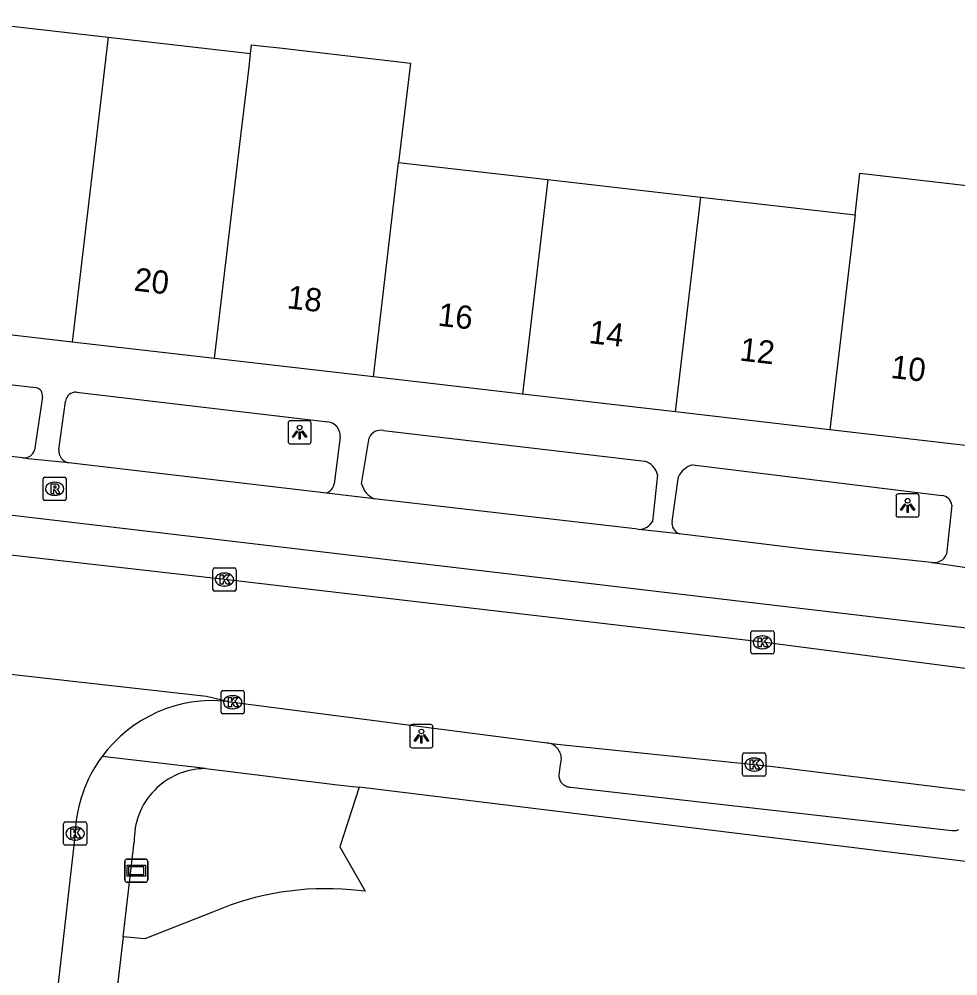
# Model space of a CAD drawing. Extents: x 161696 to 162377, y 380761 to 381673.
# Drawn here: x 162185.51 to 162225.99, y 380898.88 to 380940.12 of the extents above; entities that cross this region are included whole.
import ezdxf

# ---------------------------------------------------------------- set-up
doc = ezdxf.new("R2010")
doc.units = 0
for name, color, linetype in [('IMGEO_Groenvoorziening', 7, 'Continuous'), ('IMGEO_Kolk', 7, 'Continuous'), ('IMGEO_Lichtpunt', 7, 'Continuous'), ('IMGEO_Pand', 7, 'Continuous'), ('IMGEO_Pand_nummerreeks', 7, 'Continuous'), ('IMGEO_Rijbaan_lokaal_open', 7, 'Continuous'), ('IMGEO_Rioolput', 7, 'Continuous'), ('IMGEO_Straatnaambord', 7, 'Continuous'), ('IMGEO_Voetpad_open', 7, 'Continuous')]:
    doc.layers.add(name, color=color, linetype=linetype)

msp = doc.modelspace()

# ---------------------------------------------------------------- linework, layer by layer
at = {"layer": 'IMGEO_Groenvoorziening'}
for points in [[(162200.165, 380907.008), (162199.338, 380904.436), (162200.43, 380902.525), (162199.808, 380902.59)], [(162193.894, 380901.643), (162190.926, 380900.482), (162189.996, 380900.56)]]:
    msp.add_lwpolyline(points, dxfattribs=at)
msp.add_arc((162198.732, 380890.373), 12.265, 84.9648, 113.2301, dxfattribs=at)
at = {"layer": 'IMGEO_Kolk'}
for p, q in [((162193.935, 380916.461), (162194.787, 380916.461)), ((162193.86, 380915.535), (162193.86, 380916.387)), ((162194.348, 380916.241), (162194.373, 380916.241)), ((162194.861, 380916.387), (162194.861, 380915.535)), ((162194.371, 380915.681), (162194.346, 380915.681)), ((162194.787, 380915.461), (162193.935, 380915.461)), ((162217.057, 380912.831), (162217.057, 380913.683)), ((162217.132, 380913.757), (162217.984, 380913.757)), ((162217.545, 380913.537), (162217.57, 380913.537)), ((162218.058, 380913.683), (162218.058, 380912.831)), ((162217.984, 380912.757), (162217.132, 380912.757)), ((162217.568, 380912.977), (162217.543, 380912.977)), ((162194.215, 380910.249), (162194.215, 380911.101)), ((162194.29, 380911.175), (162195.142, 380911.175)), ((162195.216, 380911.101), (162195.216, 380910.249)), ((162194.703, 380910.955), (162194.728, 380910.955)), ((162194.726, 380910.395), (162194.701, 380910.395)), ((162195.142, 380910.175), (162194.29, 380910.175)), ((162216.702, 380907.561), (162216.702, 380908.413)), ((162216.777, 380908.487), (162217.629, 380908.487)), ((162217.19, 380908.267), (162217.215, 380908.267)), ((162217.703, 380908.413), (162217.703, 380907.561)), ((162217.629, 380907.487), (162216.777, 380907.487)), ((162217.213, 380907.707), (162217.188, 380907.707)), ((162187.422, 380904.587), (162187.422, 380905.439)), ((162187.497, 380905.513), (162188.349, 380905.513)), ((162187.91, 380905.293), (162187.935, 380905.293)), ((162188.423, 380905.439), (162188.423, 380904.587)), ((162188.349, 380904.513), (162187.497, 380904.513)), ((162187.933, 380904.733), (162187.908, 380904.733))]:
    msp.add_line(p, q, dxfattribs=at)
for points in [[(162193.935, 380916.461), (162194.787, 380916.461)], [(162193.86, 380915.535), (162193.86, 380916.387)], [(162194.181, 380916.161), (162194.304, 380916.161), (162194.304, 380916.01), (162194.434, 380916.161), (162194.598, 380916.161), (162194.452, 380916.01), (162194.605, 380915.761), (162194.453, 380915.761), (162194.368, 380915.925), (162194.304, 380915.858), (162194.304, 380915.761), (162194.181, 380915.761), (162194.181, 380916.161)], [(162194.861, 380916.387), (162194.861, 380915.535)], [(162194.787, 380915.461), (162193.935, 380915.461)], [(162217.057, 380912.831), (162217.057, 380913.683)], [(162217.132, 380913.757), (162217.984, 380913.757)], [(162218.058, 380913.683), (162218.058, 380912.831)], [(162217.378, 380913.457), (162217.501, 380913.457), (162217.501, 380913.306), (162217.631, 380913.457), (162217.795, 380913.457), (162217.649, 380913.306), (162217.802, 380913.057), (162217.65, 380913.057), (162217.565, 380913.221), (162217.501, 380913.154), (162217.501, 380913.057), (162217.378, 380913.057), (162217.378, 380913.457)], [(162217.984, 380912.757), (162217.132, 380912.757)], [(162194.215, 380910.249), (162194.215, 380911.101)], [(162194.29, 380911.175), (162195.142, 380911.175)], [(162195.216, 380911.101), (162195.216, 380910.249)], [(162194.536, 380910.875), (162194.659, 380910.875), (162194.659, 380910.724), (162194.789, 380910.875), (162194.953, 380910.875), (162194.807, 380910.724), (162194.96, 380910.475), (162194.808, 380910.475), (162194.723, 380910.639), (162194.659, 380910.572), (162194.659, 380910.475), (162194.536, 380910.475), (162194.536, 380910.875)], [(162195.142, 380910.175), (162194.29, 380910.175)], [(162216.702, 380907.561), (162216.702, 380908.413)], [(162216.777, 380908.487), (162217.629, 380908.487)], [(162217.023, 380908.187), (162217.146, 380908.187), (162217.146, 380908.036), (162217.276, 380908.187), (162217.44, 380908.187), (162217.294, 380908.036), (162217.447, 380907.787), (162217.295, 380907.787), (162217.21, 380907.951), (162217.146, 380907.884), (162217.146, 380907.787), (162217.023, 380907.787), (162217.023, 380908.187)], [(162217.703, 380908.413), (162217.703, 380907.561)], [(162217.629, 380907.487), (162216.777, 380907.487)], [(162187.422, 380904.587), (162187.422, 380905.439)], [(162187.497, 380905.513), (162188.349, 380905.513)], [(162188.423, 380905.439), (162188.423, 380904.587)], [(162187.743, 380905.213), (162187.866, 380905.213), (162187.866, 380905.062), (162187.996, 380905.213), (162188.16, 380905.213), (162188.014, 380905.062), (162188.167, 380904.813), (162188.015, 380904.813), (162187.93, 380904.977), (162187.866, 380904.91), (162187.866, 380904.813), (162187.743, 380904.813), (162187.743, 380905.213)], [(162188.349, 380904.513), (162187.497, 380904.513)]]:
    msp.add_lwpolyline(points, dxfattribs=at)
for centre, start, end in [((162193.937, 380916.385), 91.552, 178.448), ((162193.937, 380916.385), 91.552, 178.448), ((162194.785, 380916.385), 1.552, 88.448), ((162194.785, 380916.385), 1.552, 88.448), ((162193.937, 380915.537), 181.552, 268.448), ((162193.937, 380915.537), 181.552, 268.448), ((162194.785, 380915.537), 271.552, 358.448), ((162194.785, 380915.537), 271.552, 358.448), ((162217.134, 380913.681), 91.552, 178.448), ((162217.134, 380913.681), 91.552, 178.448), ((162217.982, 380913.681), 1.552, 88.448), ((162217.982, 380913.681), 1.552, 88.448), ((162217.134, 380912.833), 181.552, 268.448), ((162217.134, 380912.833), 181.552, 268.448), ((162217.982, 380912.833), 271.552, 358.448), ((162217.982, 380912.833), 271.552, 358.448), ((162194.292, 380911.099), 91.552, 178.448), ((162194.292, 380911.099), 91.552, 178.448), ((162195.14, 380911.099), 1.552, 88.448), ((162195.14, 380911.099), 1.552, 88.448), ((162194.292, 380910.251), 181.552, 268.448), ((162194.292, 380910.251), 181.552, 268.448), ((162195.14, 380910.251), 271.552, 358.448), ((162195.14, 380910.251), 271.552, 358.448), ((162216.779, 380908.411), 91.552, 178.448), ((162216.779, 380908.411), 91.552, 178.448), ((162217.627, 380908.411), 1.552, 88.448), ((162217.627, 380908.411), 1.552, 88.448), ((162216.779, 380907.563), 181.552, 268.448), ((162216.779, 380907.563), 181.552, 268.448), ((162217.627, 380907.563), 271.552, 358.448), ((162217.627, 380907.563), 271.552, 358.448), ((162187.499, 380905.437), 91.552, 178.448), ((162187.499, 380905.437), 91.552, 178.448), ((162188.347, 380905.437), 1.552, 88.448), ((162188.347, 380905.437), 1.552, 88.448), ((162187.499, 380904.589), 181.552, 268.448), ((162187.499, 380904.589), 181.552, 268.448), ((162188.347, 380904.589), 271.552, 358.448), ((162188.347, 380904.589), 271.552, 358.448)]:
    msp.add_arc(centre, 0.0765, start, end, dxfattribs=at)
for centre, major_axis, ratio, start_param, end_param in [((162194.347, 380915.961), (-0.387, 0.002), 0.722429, 4.712389, 7.853982), ((162194.372, 380915.961), (-0.39, 0.002), 0.717154, 1.570796, 4.712389), ((162217.544, 380913.257), (-0.387, 0.002), 0.722429, 4.712389, 7.853982), ((162217.569, 380913.257), (-0.39, 0.002), 0.717154, 1.570796, 4.712389), ((162194.702, 380910.675), (-0.387, 0.002), 0.722429, 4.712389, 7.853982), ((162194.727, 380910.675), (-0.39, 0.002), 0.717154, 1.570796, 4.712389), ((162217.189, 380907.987), (-0.387, 0.002), 0.722429, 4.712389, 7.853982), ((162217.214, 380907.987), (-0.39, 0.002), 0.717154, 1.570796, 4.712389), ((162187.909, 380905.013), (-0.387, 0.002), 0.722429, 4.712389, 7.853982), ((162187.934, 380905.013), (-0.39, 0.002), 0.717154, 1.570796, 4.712389)]:
    msp.add_ellipse(centre, major_axis=major_axis, ratio=ratio, start_param=start_param, end_param=end_param, dxfattribs=at)
at = {"layer": 'IMGEO_Lichtpunt'}
for p, q in [((162197.103, 380922.712), (162197.103, 380921.905)), ((162197.103, 380922.712), (162197.103, 380921.905)), ((162198.005, 380922.807), (162197.197, 380922.807)), ((162198.005, 380922.807), (162197.197, 380922.807)), ((162198.099, 380921.905), (162198.099, 380922.712)), ((162198.099, 380921.905), (162198.099, 380922.712)), ((162197.197, 380921.811), (162198.005, 380921.811)), ((162197.197, 380921.811), (162198.005, 380921.811)), ((162223.318, 380919.559), (162223.318, 380918.752)), ((162223.318, 380919.559), (162223.318, 380918.752)), ((162224.22, 380919.654), (162223.412, 380919.654)), ((162224.22, 380919.654), (162223.412, 380919.654)), ((162224.314, 380918.752), (162224.314, 380919.559)), ((162224.314, 380918.752), (162224.314, 380919.559)), ((162223.412, 380918.658), (162224.22, 380918.658)), ((162223.412, 380918.658), (162224.22, 380918.658)), ((162202.354, 380909.614), (162202.354, 380908.807)), ((162202.354, 380909.614), (162202.354, 380908.807)), ((162203.256, 380909.709), (162202.448, 380909.709)), ((162203.256, 380909.709), (162202.448, 380909.709)), ((162203.35, 380908.807), (162203.35, 380909.614)), ((162203.35, 380908.807), (162203.35, 380909.614)), ((162202.448, 380908.713), (162203.256, 380908.713)), ((162202.448, 380908.713), (162203.256, 380908.713))]:
    msp.add_line(p, q, dxfattribs=at)
for points in [[(162197.477, 380922.376), (162197.516, 380922.348), (162197.328, 380922.086), (162197.29, 380922.113), (162197.477, 380922.376)], [(162197.579, 380922.328), (162197.626, 380922.328), (162197.626, 380922.006), (162197.579, 380922.006), (162197.579, 380922.328)], [(162197.689, 380922.348), (162197.727, 380922.375), (162197.914, 380922.113), (162197.875, 380922.085), (162197.689, 380922.348)], [(162223.692, 380919.223), (162223.731, 380919.195), (162223.543, 380918.933), (162223.505, 380918.96), (162223.692, 380919.223)], [(162223.794, 380919.175), (162223.841, 380919.175), (162223.841, 380918.853), (162223.794, 380918.853), (162223.794, 380919.175)], [(162223.904, 380919.195), (162223.942, 380919.222), (162224.129, 380918.96), (162224.09, 380918.932), (162223.904, 380919.195)], [(162202.728, 380909.278), (162202.767, 380909.25), (162202.579, 380908.988), (162202.541, 380909.015), (162202.728, 380909.278)], [(162202.83, 380909.23), (162202.877, 380909.23), (162202.877, 380908.908), (162202.83, 380908.908), (162202.83, 380909.23)], [(162202.94, 380909.25), (162202.978, 380909.277), (162203.165, 380909.015), (162203.126, 380908.987), (162202.94, 380909.25)]]:
    msp.add_lwpolyline(points, dxfattribs=at)
for centre in [(162197.602, 380922.51), (162223.817, 380919.357), (162202.853, 380909.412)]:
    msp.add_circle(centre, 0.0994, dxfattribs=at)
for centre, start, end in [((162197.197, 380922.712), 90, 180), ((162197.197, 380922.712), 90, 180), ((162198.005, 380922.712), 0, 90), ((162198.005, 380922.712), 0, 90), ((162197.197, 380921.905), 180, 270), ((162197.197, 380921.905), 180, 270), ((162198.005, 380921.905), 270, 0), ((162198.005, 380921.905), 270, 360), ((162223.412, 380919.559), 90, 180), ((162223.412, 380919.559), 90, 180), ((162224.22, 380919.559), 0, 90), ((162224.22, 380919.559), 0, 90), ((162223.412, 380918.752), 180, 270), ((162223.412, 380918.752), 180, 270), ((162224.22, 380918.752), 270, 0), ((162224.22, 380918.752), 270, 360), ((162202.448, 380909.614), 90, 180), ((162202.448, 380909.614), 90, 180), ((162203.256, 380909.614), 0, 90), ((162203.256, 380909.614), 0, 90), ((162202.448, 380908.807), 180, 270), ((162202.448, 380908.807), 180, 270), ((162203.256, 380908.807), 270, 0), ((162203.256, 380908.807), 270, 360)]:
    msp.add_arc(centre, 0.0946, start, end, dxfattribs=at)
at = {"layer": 'IMGEO_Pand'}
for points in [[(162182.082, 380936.203), (162182.337, 380938.426), (162182.537, 380940.116), (162189.348, 380939.336)], [(162189.348, 380939.336), (162188.886, 380935.424), (162187.797, 380926.197)], [(162189.348, 380939.336), (162195.488, 380938.633)], [(162195.488, 380938.633), (162195.532, 380939.009), (162195.906, 380938.966), (162196.729, 380938.872), (162202.378, 380938.225), (162201.872, 380933.936)], [(162193.937, 380925.486), (162195.026, 380934.72), (162195.419, 380938.052), (162195.488, 380938.633)], [(162200.781, 380924.694), (162201.872, 380933.936)], [(162201.872, 380933.936), (162208.311, 380933.198)], [(162221.551, 380931.68), (162221.756, 380933.47), (162227.997, 380932.755)], [(162208.311, 380933.198), (162207.219, 380923.949)], [(162208.311, 380933.198), (162214.905, 380932.442)], [(162213.812, 380923.186), (162214.905, 380932.442)], [(162214.905, 380932.442), (162221.551, 380931.68)], [(162221.551, 380931.68), (162220.458, 380922.418)], [(162187.797, 380926.197), (162180.993, 380926.984)], [(162193.937, 380925.486), (162187.797, 380926.197)], [(162200.781, 380924.694), (162193.937, 380925.486)], [(162207.219, 380923.949), (162200.781, 380924.694)], [(162213.812, 380923.186), (162207.219, 380923.949)], [(162220.458, 380922.418), (162213.812, 380923.186)], [(162226.693, 380921.696), (162220.458, 380922.418)]]:
    msp.add_lwpolyline(points, dxfattribs=at)
at = {"layer": 'IMGEO_Rijbaan_lokaal_open'}
for points in [[(162234.33, 380911.127), (162231.163, 380911.496), (162217.557, 380913.256), (162194.36, 380915.961), (162175.911, 380918.063)], [(162194.485, 380910.711), (162193.581, 380910.917), (162177.833, 380912.69), (162177.053, 380912.703)], [(162194.485, 380910.711), (162194.716, 380910.676), (162208.277, 380908.928)], [(162208.277, 380908.928), (162208.7, 380908.873), (162217.892, 380907.916), (162227.216, 380906.767)], [(162187.923, 380905.013), (162186.025, 380888.313), (162184.491, 380874.927), (162183.917, 380870.085)]]:
    msp.add_lwpolyline(points, dxfattribs=at)
for centre, radius, start, end in [((162193.859, 380904.805), 5.939, 83.9535, 143.5676), ((162193.863, 380904.802), 5.944, 143.566, 177.9662)]:
    msp.add_arc(centre, radius, start, end, dxfattribs=at)
at = {"layer": 'IMGEO_Rioolput'}
for p, q in [((162186.538, 380919.448), (162186.538, 380920.3)), ((162186.613, 380920.374), (162187.465, 380920.374)), ((162187.026, 380920.154), (162187.051, 380920.154)), ((162187.539, 380920.3), (162187.539, 380919.448)), ((162187.465, 380919.374), (162186.613, 380919.374)), ((162187.049, 380919.594), (162187.024, 380919.594))]:
    msp.add_line(p, q, dxfattribs=at)
for points in [[(162186.538, 380919.448), (162186.538, 380920.3)], [(162186.613, 380920.374), (162187.465, 380920.374)], [(162187.539, 380920.3), (162187.539, 380919.448)], [(162187.127, 380920.072), (162186.875, 380920.074), (162186.875, 380919.674)], [(162186.875, 380919.674), (162186.999, 380919.674), (162186.999, 380919.836), (162187.01, 380919.836)], [(162187.053, 380919.993), (162186.999, 380919.993), (162186.999, 380919.912)], [(162186.999, 380919.912), (162187.051, 380919.912)], [(162187.057, 380919.807), (162187.128, 380919.674), (162187.268, 380919.674), (162187.203, 380919.8)], [(162187.465, 380919.374), (162186.613, 380919.374)]]:
    msp.add_lwpolyline(points, dxfattribs=at)
for centre, radius, start, end in [((162186.615, 380920.298), 0.0765, 91.552, 178.448), ((162186.615, 380920.298), 0.0765, 91.552, 178.448), ((162187.463, 380920.298), 0.0765, 1.552, 88.448), ((162187.463, 380920.298), 0.0765, 1.552, 88.448), ((162187.009, 380919.783), 0.0533, 26.0293, 88.6989), ((162187.035, 380920.101), 0.19, 274.7715, 282.9687), ((162187.059, 380919.897), 0.0964, 77.0061, 93.1865), ((162187.073, 380919.954), 0.0378, 276.6634, 79.6772), ((162187.126, 380919.962), 0.109, 350.3612, 89.416), ((162187.124, 380919.962), 0.112, 277.5842, 350.9817), ((162187.108, 380919.747), 0.108, 29.5134, 73.7905), ((162186.615, 380919.45), 0.0765, 181.552, 268.448), ((162186.615, 380919.45), 0.0765, 181.552, 268.448), ((162187.463, 380919.45), 0.0765, 271.552, 358.448), ((162187.463, 380919.45), 0.0765, 271.552, 358.448)]:
    msp.add_arc(centre, radius, start, end, dxfattribs=at)
for centre, major_axis, ratio, start_param, end_param in [((162187.025, 380919.874), (-0.387, 0.002), 0.722429, 4.712389, 7.853982), ((162187.05, 380919.874), (-0.39, 0.002), 0.717154, 1.570796, 4.712389)]:
    msp.add_ellipse(centre, major_axis=major_axis, ratio=ratio, start_param=start_param, end_param=end_param, dxfattribs=at)
at = {"layer": 'IMGEO_Straatnaambord'}
for p, q in [((162190.064, 380903.016), (162190.064, 380903.816)), ((162190.064, 380903.816), (162190.064, 380903.016)), ((162190.164, 380903.916), (162190.954, 380903.916)), ((162190.954, 380903.916), (162190.164, 380903.916)), ((162191.054, 380903.816), (162191.054, 380903.016)), ((162191.054, 380903.016), (162191.054, 380903.816)), ((162190.954, 380902.916), (162190.164, 380902.916)), ((162190.164, 380902.916), (162190.954, 380902.916))]:
    msp.add_line(p, q, dxfattribs=at)
for points in [[(162190.165, 380903.648), (162190.953, 380903.648), (162190.953, 380903.184), (162190.165, 380903.184), (162190.165, 380903.648)], [(162190.23, 380903.583), (162190.23, 380903.249), (162190.888, 380903.249), (162190.888, 380903.583), (162190.23, 380903.583)]]:
    msp.add_lwpolyline(points, dxfattribs=at)
for centre, start, end in [((162190.164, 380903.816), 90, 180), ((162190.164, 380903.816), 90, 180), ((162190.954, 380903.816), 0, 90), ((162190.954, 380903.816), 360, 90), ((162190.164, 380903.016), 180, 270), ((162190.164, 380903.016), 180, 270), ((162190.954, 380903.016), 270, 0), ((162190.954, 380903.016), 270, 0)]:
    msp.add_arc(centre, 0.1, start, end, dxfattribs=at)
at = {"layer": 'IMGEO_Voetpad_open'}
for points in [[(162175.244, 380925.487), (162186.232, 380924.235)], [(162186.513, 380923.835), (162186.172, 380921.544)], [(162187.982, 380924.037), (162198.82, 380922.76)], [(162187.214, 380921.57), (162187.507, 380923.638)], [(162185.669, 380921.214), (162174.637, 380922.44)], [(162201.22, 380922.384), (162212.489, 380921.068)], [(162199.35, 380922.105), (162199.096, 380920.089)], [(162200.275, 380920.087), (162200.594, 380922.067)], [(162187.648, 380920.991), (162185.902, 380921.167), (162185.669, 380921.214)], [(162198.762, 380919.679), (162187.648, 380920.991)], [(162214.556, 380920.903), (162225.298, 380919.583)], [(162213.037, 380920.478), (162212.812, 380918.469)], [(162213.662, 380918.467), (162213.937, 380920.406)], [(162176.171, 380918.467), (162176.321, 380919.783), (162233.539, 380913.036), (162236.135, 380912.951), (162238.109, 380913.042), (162241.292, 380913.209), (162242.624, 380913.349), (162246.189, 380913.913), (162247.621, 380914.14), (162247.804, 380913.155)], [(162200.813, 380919.445), (162198.762, 380919.679)], [(162212.234, 380918.123), (162212.072, 380918.141), (162200.813, 380919.445)], [(162225.721, 380919.173), (162225.494, 380917.053)], [(162213.961, 380917.936), (162212.234, 380918.123)], [(162224.855, 380916.697), (162219.5, 380917.26), (162213.961, 380917.936)], [(162226.845, 380916.402), (162224.992, 380916.663), (162224.855, 380916.697)], [(162226.015, 380905.172), (162225.976, 380905.156), (162225.936, 380905.144), (162225.895, 380905.135), (162225.854, 380905.129), (162225.812, 380905.128), (162225.77, 380905.13), (162225.729, 380905.136), (162209.283, 380906.999), (162209.253, 380907.001), (162209.207, 380907.008), (162209.163, 380907.018), (162209.119, 380907.033), (162209.077, 380907.051), (162209.037, 380907.073), (162208.999, 380907.099), (162208.963, 380907.127), (162208.93, 380907.159), (162208.9, 380907.194), (162208.874, 380907.231), (162208.85, 380907.271), (162208.831, 380907.312), (162208.815, 380907.355), (162208.803, 380907.399), (162208.795, 380907.444), (162208.791, 380907.49), (162208.791, 380907.536), (162208.845, 380907.993), (162208.864, 380908.055), (162208.878, 380908.116), (162208.885, 380908.179), (162208.887, 380908.241), (162208.884, 380908.304), (162208.875, 380908.366), (162208.86, 380908.426), (162208.84, 380908.486), (162208.815, 380908.543), (162208.785, 380908.598), (162208.75, 380908.65), (162208.71, 380908.698), (162208.667, 380908.743), (162208.619, 380908.784), (162208.568, 380908.821), (162208.514, 380908.852), (162208.458, 380908.879), (162208.399, 380908.901), (162208.339, 380908.917), (162208.277, 380908.928)], [(162193.546, 380907.814), (162189.081, 380908.332)], [(162193.546, 380907.814), (162194.261, 380907.731), (162199.241, 380907.121), (162200.165, 380907.008)], [(162237.275, 380903.064), (162235.212, 380903.018), (162230.686, 380903.218), (162226.196, 380903.822), (162200.165, 380907.008)], [(162189.996, 380900.56), (162190.473, 380904.639)], [(162189.996, 380900.56), (162189.655, 380897.636), (162188.777, 380889.994), (162186.359, 380869.537)]]:
    msp.add_lwpolyline(points, dxfattribs=at)
for centre, radius, start, end in [((162186.154, 380923.882), 0.362, 352.6113, 77.5648), ((162187.953, 380923.589), 0.449, 86.3515, 173.709), ((162198.748, 380922.16), 0.604, 354.7647, 83.1921), ((162201.099, 380921.846), 0.551, 77.3137, 156.4007), ((162185.729, 380921.67), 0.46, 262.4635, 344.0714), ((162187.759, 380921.526), 0.546, 175.3907, 258.3174), ((162212.213, 380920.262), 0.852, 14.6737, 71.099), ((162214.778, 380919.992), 0.938, 103.7154, 153.8071), ((162198.5, 380920.233), 0.613, 295.2761, 346.3891), ((162201.203, 380920.318), 0.957, 194.0021, 245.9243), ((162225.252, 380919.112), 0.473, 7.4011, 84.3871), ((162212.223, 380918.797), 0.674, 270.9057, 330.9051), ((162214.151, 380918.393), 0.495, 171.3558, 247.4109), ((162224.951, 380917.277), 0.587, 260.6201, 337.6261), ((162193.552, 380904.734), 3.08, 90.1069, 181.7637)]:
    msp.add_arc(centre, radius, start, end, dxfattribs=at)

# ---------------------------------------------------------------- texts
at = {"layer": 'IMGEO_Pand_nummerreeks'}
for s, rotation, p in [('20', 353.4224, (162190.429, 380928.418)), ('18', 353.4224, (162197.027, 380927.657)), ('16', 353.4197, (162203.532, 380926.907)), ('14', 353.4197, (162210.041, 380926.156)), ('12', 353.4197, (162216.546, 380925.405)), ('10', 353.4224, (162223.06, 380924.654))]:
    msp.add_text(s, height=1, rotation=rotation, dxfattribs=at).set_placement(p)

doc.saveas('drawing.dxf')
